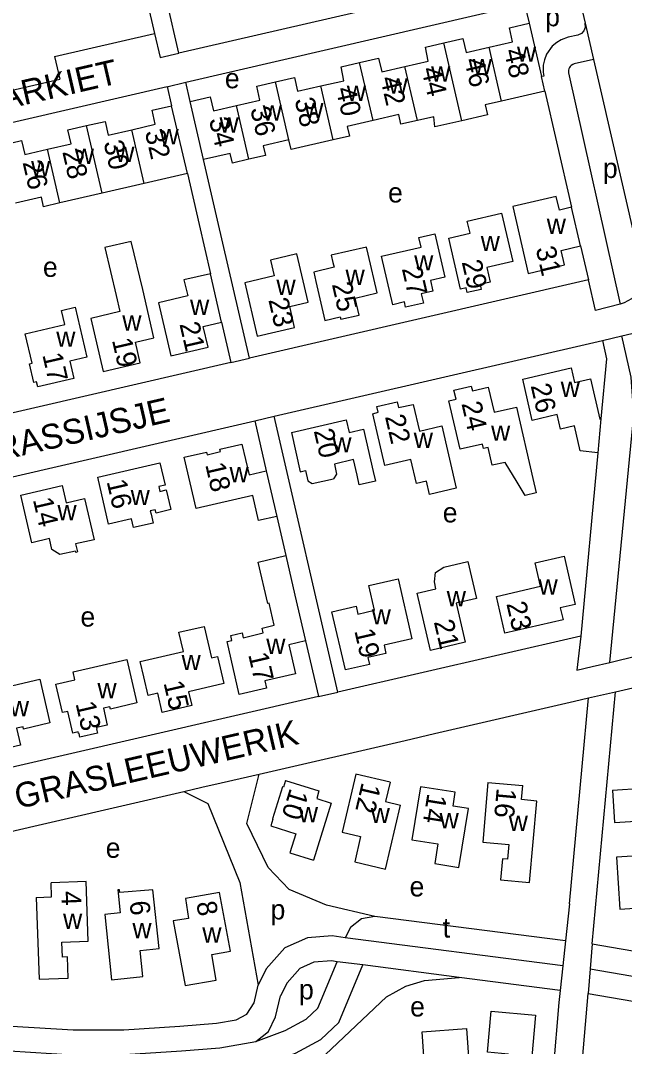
# Model space of a CAD drawing. Extents: x 155696 to 157795, y 382328 to 384028.
# Drawn here: x 156705.6 to 156827.2, y 383139.6 to 383346.1 of the extents above; entities that cross this region are included whole.
import ezdxf

# ---------------------------------------------------------------- set-up
doc = ezdxf.new("R2010")
doc.units = 0
for name, color, linetype in [('BLT_Basislijn', 7, 'Continuous'), ('BLT_Bebouwing', 7, 'Continuous'), ('BLT_Centroide', 7, 'Continuous'), ('BLT_Huisnummer', 7, 'Continuous'), ('BLT_Huisnummer_ tussenligend', 7, 'Continuous'), ('BLT_Onderverdeling_panden', 7, 'Continuous'), ('BLT_Straatnaam', 7, 'Continuous')]:
    doc.layers.add(name, color=color, linetype=linetype)

msp = doc.modelspace()

# ---------------------------------------------------------------- linework, layer by layer
at = {"layer": 'BLT_Basislijn'}
for p, q in [((156819.25, 383345.11), (156819.26, 383345.53)), ((156819.26, 383345.53), (156820.95, 383338.22)), ((156712.46, 383338.83), (156732.56, 383343.47)), ((156712.46, 383338.83), (156713.51, 383334.26)), ((156685.11, 383327.7), (156713.51, 383334.26)), ((156735.03, 383332.74), (156738.84, 383333.63)), ((156826.61, 383282.58), (156831.79, 383283.78)), ((156822.71, 383281.68), (156826.61, 383282.58)), ((156747.95, 383277.24), (156751.67, 383278.1)), ((156752.73, 383265.51), (156756.62, 383266.41)), ((156821.81, 383259.06), (156818.36, 383222.17)), ((156765.55, 383209.98), (156769.45, 383210.88)), ((156819.94, 383209.71), (156825.35, 383210.96)), ((156788.92, 383202.54), (156817.14, 383209.06)), ((156817.14, 383209.06), (156819.94, 383209.71)), ((156782.99, 383201.17), (156788.92, 383202.54)), ((156753.65, 383194.4), (156782.99, 383201.17)), ((156746.01, 383192.63), (156753.65, 383194.4)), ((156742.11, 383191.73), (156746.01, 383192.63)), ((156693.58, 383180.52), (156738.44, 383190.88)), ((156738.44, 383190.88), (156742.11, 383191.73)), ((156820.68, 383160.19), (156820.26, 383155.19)), ((156820.26, 383155.19), (156819.83, 383150.19)), ((156813.95, 383148.39), (156810.53, 383107.98))]:
    msp.add_line(p, q, dxfattribs=at)
for points in [[(156664.33, 383327.71), (156659.04, 383350.61), (156727.27, 383366.37), (156732.56, 383343.47)], [(156809.62, 383356.14), (156737.49, 383339.48), (156735.12, 383349.71)], [(156738.84, 383333.63), (156807.07, 383349.4)], [(156807.07, 383349.4), (156807.97, 383345.5)], [(156818.46, 383348.95), (156819.26, 383345.53)], [(156819.25, 383345.11), (156819.24, 383344.65), (156819.01, 383343.95), (156818.49, 383343.46), (156817.76, 383343.13), (156815.81, 383342.68), (156814.39, 383342.17), (156813.56, 383341.62), (156812.63, 383340.89), (156811.49, 383339.28), (156811.04, 383338.17), (156810.81, 383337.09), (156810.8, 383335.66), (156810.94, 383334.88), (156810.45, 383334.78)], [(156732.56, 383343.47), (156733.68, 383338.6), (156737.49, 383339.48)], [(156820.95, 383338.22), (156817.05, 383337.32), (156816.74, 383337.21), (156816.45, 383337.03), (156816.24, 383336.82), (156816.08, 383336.58), (156815.98, 383336.34), (156815.9, 383336.08), (156815.89, 383335.79), (156815.93, 383335.52), (156826.3, 383288.94)], [(156820.95, 383338.22), (156830.69, 383296.04), (156830.81, 383294.33), (156830.54, 383292.75), (156829.66, 383291.07), (156828.58, 383290.07), (156827.13, 383289.21), (156826.3, 383288.94)], [(156667.81, 383313.12), (156666.88, 383317.01), (156735.12, 383332.78)], [(156735.12, 383332.78), (156736.01, 383328.9)], [(156739.74, 383329.74), (156738.84, 383333.63)], [(156811.12, 383331.86), (156813.49, 383321.63)], [(156813.49, 383321.63), (156816.51, 383308.47)], [(156745.25, 383305.87), (156742.45, 383318.06)], [(156739.18, 383315.26), (156741.53, 383305.01)], [(156819.9, 383293.86), (156751.67, 383278.1), (156745.25, 383305.87)], [(156741.53, 383305.01), (156743.83, 383295.07)], [(156818.33, 383300.68), (156819.9, 383293.86)], [(156826.3, 383288.94), (156821.33, 383287.66), (156819.9, 383293.86)], [(156746.08, 383285.32), (156747.95, 383277.24), (156679.71, 383261.48), (156673.3, 383289.24)], [(156756.62, 383266.41), (156822.71, 383281.68)], [(156822.71, 383281.68), (156823.58, 383277.95), (156822.42, 383265.9)], [(156828.53, 383274.26), (156826.61, 383282.58)], [(156824.25, 383216.86), (156829.03, 383266.72), (156828.53, 383274.26)], [(156818.36, 383222.17), (156769.45, 383210.88), (156756.62, 383266.41)], [(156682.73, 383249.34), (156752.73, 383265.51), (156755.05, 383255.43)], [(156762.96, 383221.21), (156765.55, 383209.98), (156695.56, 383193.81), (156682.73, 383249.34)], [(156757.17, 383246.25), (156759, 383238.36)], [(156818.36, 383222.17), (156817.57, 383215.32), (156820.65, 383216.03), (156824.25, 383216.86)], [(156824.25, 383216.86), (156840.78, 383220.93)], [(156825.35, 383210.96), (156842.25, 383214.86)], [(156820.68, 383160.19), (156825.35, 383210.96)], [(156816.07, 383168.29), (156819.94, 383209.71)], [(156776.9, 383165.74), (156767.16, 383167.97), (156759.7, 383171.13), (156755.46, 383175.55), (156751.14, 383184.47), (156753.65, 383194.4)], [(156738.44, 383190.88), (156743.29, 383188.47), (156749.72, 383172.56), (156753.45, 383151.93)], [(156816.07, 383168.29), (156815.27, 383160.79)], [(156776.9, 383165.74), (156774.25, 383165.23), (156772.02, 383163.5), (156770.95, 383161.46)], [(156815.27, 383160.79), (156776.9, 383165.74)], [(156624.06, 383159.74), (156634.99, 383161.39), (156641.65, 383161.73), (156646.47, 383160.41), (156654.67, 383156.22), (156664.2, 383151.34), (156679.47, 383145.14), (156688.43, 383141.04), (156694.45, 383139.66), (156703.4, 383138.69), (156716.03, 383137.88), (156726.59, 383137.94), (156738.01, 383138.69), (156745.69, 383139.31), (156752.98, 383140.57)], [(156770.95, 383161.46), (156768.32, 383161.8), (156763.38, 383161.46), (156758.79, 383159.39), (156755.06, 383155.2), (156753.45, 383151.93)], [(156814.74, 383155.82), (156770.95, 383161.46)], [(156815.27, 383160.79), (156814.74, 383155.82)], [(156820.68, 383160.19), (156846.73, 383155.72)], [(156769.34, 383156.63), (156768.17, 383156.78), (156764.62, 383156.53), (156761.81, 383155.27), (156759.25, 383152.39), (156757.94, 383149.73)], [(156625.19, 383154.85), (156635.49, 383156.41), (156641.1, 383156.7), (156644.65, 383155.72), (156652.4, 383151.77), (156662.12, 383146.79), (156677.48, 383140.55), (156686.81, 383136.28), (156693.62, 383134.72), (156702.97, 383133.7), (156715.88, 383132.88), (156726.77, 383132.94), (156738.37, 383133.7), (156746.32, 383134.34), (156754.28, 383135.72), (156760.97, 383138.19), (156766.06, 383140.98), (156769.64, 383144.39), (156774.48, 383155.97)], [(156752.98, 383140.57), (156758.89, 383142.75), (156763.08, 383145.05), (156765.44, 383147.29), (156769.34, 383156.63)], [(156774.48, 383155.97), (156769.34, 383156.63)], [(156793.91, 383153.46), (156774.48, 383155.97)], [(156814.74, 383155.82), (156814.21, 383150.85)], [(156820.26, 383155.19), (156846.76, 383150.64)], [(156767.48, 383098.04), (156766.03, 383104.42), (156756.96, 383125.83), (156759.58, 383130.94), (156779.26, 383149.57), (156783.18, 383151.73), (156786.92, 383152.81), (156793.91, 383153.46)], [(156814.21, 383150.85), (156793.91, 383153.46)], [(156748.98, 383144.95), (156751.18, 383146.08), (156752.61, 383148.32), (156753.45, 383151.93)], [(156814.21, 383150.85), (156813.95, 383148.39)], [(156752.98, 383140.57), (156755.53, 383142.58), (156756.9, 383145.5), (156757.94, 383149.73)], [(156800.36, 383000.81), (156809.66, 383051.7), (156812.28, 383070.91), (156814.57, 383087.69), (156816.87, 383115.08), (156819.83, 383150.19)], [(156819.83, 383150.19), (156846.8, 383145.57)], [(156690.04, 383145.8), (156695.28, 383144.6), (156703.83, 383143.67), (156716.18, 383142.88), (156726.41, 383142.94), (156737.65, 383143.67), (156745.06, 383144.27), (156748.98, 383144.95)]]:
    msp.add_lwpolyline(points, dxfattribs=at)
at = {"layer": 'BLT_Bebouwing'}
for p, q in [((156807.97, 383345.5), (156810.45, 383334.78)), ((156790.81, 383341.55), (156794.61, 383342.44)), ((156794.61, 383342.44), (156795.27, 383339.61)), ((156795.27, 383339.61), (156799.93, 383340.7)), ((156770.14, 383336.76), (156773.86, 383337.61)), ((156770.7, 383333.94), (156770.14, 383336.76)), ((156811.12, 383331.86), (156810.45, 383334.78)), ((156753.19, 383332.84), (156756.9, 383333.7)), ((156753.78, 383330.04), (156753.19, 383332.84)), ((156766.02, 383332.88), (156770.7, 383333.94)), ((156732.07, 383327.99), (156736.01, 383328.9)), ((156739.18, 383315.26), (156736.01, 383328.9)), ((156742.45, 383318.06), (156739.74, 383329.74)), ((156749.07, 383328.95), (156753.78, 383330.04)), ((156732.72, 383325.2), (156732.07, 383327.99)), ((156715.11, 383324.06), (156718.85, 383324.92)), ((156715.76, 383321.27), (156715.11, 383324.06)), ((156718.85, 383324.92), (156722.61, 383325.76)), ((156722.61, 383325.76), (156723.27, 383322.97)), ((156723.27, 383322.97), (156727.98, 383324.08)), ((156727.98, 383324.08), (156732.72, 383325.2)), ((156760.06, 383320.08), (156759.61, 383322.03)), ((156768.53, 383322.04), (156760.06, 383320.08)), ((156711.02, 383320.16), (156715.76, 383321.27)), ((156818.33, 383300.68), (156816.51, 383308.47)), ((156758.91, 383193.11), (156765.67, 383191.02)), ((156799.67, 383192.69), (156806.68, 383192.06)), ((156768.16, 383188.54), (156764.59, 383177.06)), ((156779.05, 383175.25), (156782.06, 383188.14)), ((156808.03, 383172.55), (156809.53, 383188.94)), ((156793.83, 383175.61), (156795.74, 383187.46)), ((156708.74, 383169.56), (156709.33, 383153.09)), ((156722.55, 383166.1), (156723.93, 383152.97)), ((156736.34, 383164.82), (156738.74, 383151.81))]:
    msp.add_line(p, q, dxfattribs=at)
for points in [[(156799.93, 383340.7), (156804.61, 383341.78), (156804, 383344.58), (156807.97, 383345.5)], [(156782.98, 383336.79), (156787.67, 383337.87), (156787.09, 383340.67), (156790.81, 383341.55)], [(156773.86, 383337.61), (156777.68, 383338.49), (156778.32, 383335.71), (156782.98, 383336.79)], [(156756.9, 383333.7), (156760.72, 383334.6), (156761.35, 383331.82), (156766.02, 383332.88)], [(156739.74, 383329.74), (156743.79, 383330.67), (156744.43, 383327.89), (156749.07, 383328.95)], [(156811.12, 383331.86), (156802.44, 383329.85)], [(156802.44, 383329.85), (156799.13, 383329.09), (156799.59, 383327.09), (156794.42, 383325.9)], [(156785.48, 383325.95), (156782.18, 383325.17), (156781.73, 383327.12), (156776.55, 383325.94)], [(156794.42, 383325.9), (156789.02, 383324.65), (156788.79, 383326.7), (156785.48, 383325.95)], [(156776.55, 383325.94), (156771.38, 383324.73), (156771.84, 383322.8), (156768.53, 383322.04)], [(156759.61, 383322.03), (156754.43, 383320.83), (156754.89, 383318.88), (156751.57, 383318.12)], [(156701.9, 383321), (156705.8, 383321.9), (156706.44, 383319.1), (156711.02, 383320.16)], [(156751.57, 383318.12), (156748.28, 383317.36), (156747.83, 383319.31), (156742.45, 383318.06)], [(156739.18, 383315.26), (156730.48, 383313.25)], [(156730.48, 383313.25), (156722, 383311.29)], [(156713.52, 383309.33), (156710.24, 383308.56), (156709.79, 383310.52), (156704.61, 383309.32)], [(156722, 383311.29), (156713.52, 383309.33)], [(156816.51, 383308.47), (156814.07, 383307.91), (156813.44, 383310.64), (156804.69, 383308.61), (156807.8, 383295.17), (156815.1, 383296.86), (156814.43, 383299.78), (156818.33, 383300.68)], [(156730.19, 383291.92), (156727.87, 383301.59), (156722.56, 383300.35), (156724.86, 383290.69), (156725.6, 383287.47), (156719.72, 383286.11), (156722.2, 383275.4)], [(156743.83, 383295.07), (156738.5, 383293.84), (156739.25, 383290.62), (156733.36, 383289.26), (156735.84, 383278.55)], [(156746.08, 383285.32), (156743.83, 383295.07)], [(156732.44, 383282.17), (156730.19, 383291.92)], [(156735.84, 383278.55), (156743.35, 383280.28), (156742.38, 383284.47), (156746.08, 383285.32)], [(156722.2, 383275.4), (156729.71, 383277.13), (156728.74, 383281.32), (156732.44, 383282.17)], [(156818.25, 383259.42), (156817.08, 383264.46), (156814.28, 383263.81), (156813.6, 383266.73), (156808.6, 383265.57), (156806.68, 383273.87), (156816.42, 383276.12), (156817.1, 383273.2), (156820.31, 383273.93), (156822.2, 383265.85), (156822.42, 383265.9)], [(156792.84, 383271.67), (156796.34, 383272.47), (156796.56, 383271.5), (156799.75, 383272.24), (156800.91, 383267.2), (156805.41, 383268.24), (156808.73, 383253.89), (156809.36, 383250.99), (156807.18, 383250.49), (156805.54, 383253.15), (156803.14, 383257.09), (156800.56, 383256.55), (156799.71, 383260.15)], [(156799.71, 383260.15), (156798.79, 383259.93), (156798.58, 383260.79), (156794.06, 383259.76), (156791.8, 383269.49), (156793.27, 383269.84), (156792.84, 383271.67)], [(156760.11, 383263.11), (156771.14, 383265.66), (156771.72, 383263.16), (156774.62, 383263.82), (156776.59, 383255.31), (156777.02, 383253.34), (156773.77, 383252.6), (156773.37, 383254.57), (156772.65, 383257.68), (156768.79, 383256.79), (156769.18, 383254.72), (156768.61, 383253.83)], [(156822.42, 383265.9), (156821.81, 383259.06)], [(156760.11, 383263.11), (156761.92, 383255.24), (156762.95, 383255.47), (156763.43, 383253.41), (156764.33, 383252.84), (156768.61, 383253.83)], [(156757.17, 383246.25), (156753.5, 383245.41), (156752.34, 383250.45), (156740.96, 383247.82), (156738.57, 383258.14), (156743.02, 383259.18), (156743.14, 383258.66), (156745.87, 383259.29), (156745.75, 383259.81), (156750.17, 383260.82), (156751.6, 383254.63), (156755.05, 383255.43)], [(156821.81, 383259.06), (156818.25, 383259.42)], [(156755.05, 383255.43), (156757.17, 383246.25)], [(156755.35, 383228.73), (156753.44, 383237.06), (156759, 383238.36)], [(156759, 383238.36), (156760.84, 383230.39)], [(156760.84, 383230.39), (156762.96, 383221.21)], [(156749.6, 383210.4), (156747.18, 383221.08), (156748.13, 383221.3), (156747.91, 383222.27), (156750.2, 383222.8), (156750.43, 383221.82), (156754.47, 383222.81), (156754.24, 383223.78), (156756.67, 383224.34), (156755.65, 383228.8), (156755.35, 383228.73)], [(156762.96, 383221.21), (156759.6, 383220.43), (156760.96, 383214.56), (156754.76, 383213.13)], [(156754.76, 383213.13), (156755.1, 383211.66), (156749.6, 383210.4)], [(156779.97, 383192.77), (156773.1, 383194.37), (156770.35, 383182.7), (156774.04, 383181.83), (156772.89, 383176.71), (156779.05, 383175.25)], [(156758.91, 383193.11), (156758.5, 383191.77), (156758.32, 383191.83), (156756.31, 383185.36), (156756.39, 383185.34), (156755.96, 383183.96), (156761.03, 383182.39), (156759.83, 383178.53), (156764.59, 383177.06)], [(156779.97, 383192.77), (156779.05, 383188.84), (156782.06, 383188.14)], [(156799.67, 383192.69), (156798.64, 383180.7), (156803.86, 383180.21), (156803.59, 383177.26), (156802.59, 383177.35), (156802.19, 383173.09), (156808.03, 383172.55)], [(156809.53, 383188.94), (156806.43, 383189.24), (156806.68, 383192.06)], [(156765.67, 383191.02), (156765.21, 383189.44), (156768.16, 383188.54)], [(156793.09, 383190.73), (156786.13, 383191.85), (156784.37, 383181.17), (156789.61, 383180.37), (156789, 383176.39), (156793.83, 383175.61)], [(156795.74, 383187.46), (156792.66, 383187.94), (156793.09, 383190.73)], [(156824.75, 383191.16), (156830.86, 383191.55), (156830.99, 383189.5), (156833.78, 383189.68)], [(156824.75, 383191.16), (156825.17, 383184.64), (156829.42, 383184.91), (156829.86, 383177.95), (156825.58, 383177.67), (156826.25, 383167.21), (156835.24, 383167.79), (156833.78, 383189.68)], [(156708.74, 383169.56), (156711.86, 383169.69), (156711.76, 383172.52)], [(156709.33, 383153.09), (156715.19, 383153.31), (156715.03, 383157.59), (156714.05, 383157.55), (156713.94, 383160.55), (156719.22, 383160.74), (156718.81, 383172.74), (156711.76, 383172.52)], [(156723.93, 383152.97), (156730.24, 383153.64), (156729.69, 383158.85), (156733.49, 383159.26), (156732.23, 383171.12), (156725.62, 383170.54), (156725.55, 383171.09), (156725.16, 383171.06), (156725.66, 383166.44), (156722.55, 383166.1)], [(156738.8, 383169.36), (156739.42, 383165.35), (156736.34, 383164.82)], [(156738.74, 383151.81), (156744.99, 383152.92), (156744.09, 383158.07), (156747.86, 383158.75), (156745.65, 383170.54), (156738.8, 383169.36)]]:
    msp.add_lwpolyline(points, dxfattribs=at)
for points in [[(156791.79, 383302.25), (156796.09, 383303.24), (156795.53, 383305.68), (156802.43, 383307.27), (156804.68, 383297.53), (156799.47, 383296.32), (156800.15, 383293.4), (156798.1, 383292.93), (156798.32, 383291.95), (156795.5, 383291.3), (156795.27, 383292.28), (156794.15, 383292.02)], [(156778.26, 383298.61), (156786.23, 383300.45), (156785.78, 383302.4), (156789.02, 383303.14), (156791.04, 383294.38), (156788.12, 383293.7), (156788.61, 383291.59), (156786.26, 383291.04), (156786.69, 383289.17), (156783.11, 383288.34), (156782.86, 383289.41), (156780.51, 383288.86)], [(156775.6, 383299.02), (156775.25, 383300.47), (156768.16, 383298.82), (156768.49, 383297.38), (156768.72, 383296.39), (156764.63, 383295.44), (156765.07, 383293.51), (156766.87, 383285.71), (156769.94, 383286.42), (156770.05, 383285.94), (156773.73, 383286.78), (156772.94, 383290.19), (156777.4, 383291.23)], [(156761.22, 383299.08), (156755.89, 383297.85), (156756.64, 383294.64), (156750.76, 383293.28), (156753.23, 383282.56), (156760.74, 383284.3), (156759.78, 383288.49), (156763.47, 383289.34)], [(156716.61, 383288.35), (156718.94, 383278.32), (156715.53, 383277.52), (156716.35, 383274.02), (156709.05, 383272.31), (156708.81, 383273.31), (156708.29, 383273.2), (156707.42, 383276.97), (156707.93, 383277.09), (156706.56, 383283.01), (156714.53, 383284.86), (156713.87, 383287.72)], [(156776.51, 383266.9), (156777.6, 383267.21), (156777.33, 383268.39), (156781.4, 383269.34), (156781.68, 383268.16), (156784.65, 383268.75), (156785.88, 383263.42), (156790.38, 383264.46), (156793.27, 383251.93), (156787.93, 383250.69), (156787.31, 383253.37), (156785.27, 383252.9), (156784.16, 383257.73), (156778.9, 383256.51)], [(156733.67, 383257.03), (156734.7, 383252.56), (156733.41, 383252.27), (156733.64, 383251.27), (156734.93, 383251.57), (156735.84, 383247.61), (156732.87, 383246.93), (156732.72, 383247.59), (156731.72, 383247.36), (156731.87, 383246.69), (156732.28, 383244.92), (156728.33, 383244), (156727.93, 383245.74), (156723.33, 383244.68), (156721.15, 383254.12)], [(156705.69, 383250.54), (156713.97, 383252.46), (156714.77, 383248.99), (156718.47, 383249.84), (156720.39, 383241.56), (156716.69, 383240.71), (156717.05, 383239.12), (156716.72, 383239), (156716.67, 383239.22), (156713.49, 383238.57), (156711.92, 383239.6), (156711.42, 383241.77), (156707.9, 383240.96)], [(156801.39, 383230.14), (156810.25, 383232.18), (156809.17, 383236.89), (156815.01, 383238.24), (156817.25, 383228.54), (156814.25, 383227.84), (156814.8, 383225.46), (156803.09, 383222.75)], [(156785.42, 383230.82), (156789.22, 383231.7), (156788.91, 383233.05), (156789.16, 383234.99), (156790.79, 383236.06), (156795.65, 383237.19), (156797.37, 383229.74), (156793.28, 383228.8), (156795.1, 383220.91), (156788.09, 383219.28)], [(156775.85, 383216.46), (156770.99, 383215.34), (156768.29, 383227.03), (156773.16, 383228.15), (156773.52, 383226.59), (156776.84, 383227.36), (156775.7, 383232.32), (156781.58, 383233.68), (156784.37, 383221.61), (156778.77, 383220.32), (156779.15, 383218.66), (156775.54, 383217.82)], [(156734.1, 383206.81), (156733.22, 383210.67), (156731.3, 383210.22), (156730.41, 383213.97), (156729.7, 383217.02), (156738.37, 383219.05), (156737.47, 383222.94), (156742.55, 383224.11), (156744.01, 383217.77), (156745.26, 383218.06), (156746.53, 383212.6), (156739.42, 383210.96), (156740.06, 383208.19)], [(156715.11, 383207), (156714.05, 383206.76), (156712.71, 383212.47), (156716.56, 383213.36), (156716.19, 383214.99), (156726.98, 383217.48), (156729, 383208.72), (156723.71, 383207.46), (156723.6, 383207.95), (156722.28, 383207.65), (156723.07, 383204.25), (156720.89, 383203.75), (156720.95, 383203.42), (156720.89, 383203.41), (156721.07, 383202.63), (156717.55, 383201.81), (156717.37, 383202.58), (156717.3, 383202.57), (156717.23, 383202.89), (156716.11, 383202.63)], [(156695.15, 383208.27), (156698.98, 383209.15), (156698.57, 383210.95), (156709.48, 383213.47), (156711.51, 383204.68), (156706.23, 383203.43), (156706.12, 383203.91), (156704.8, 383203.61), (156705.58, 383200.2), (156698.62, 383198.59), (156697.57, 383202.95), (156696.5, 383202.69)], [(156800.32, 383146.68), (156809.28, 383145.88), (156807.54, 383126.23), (156801.53, 383126.76), (156801.94, 383131.45), (156803.21, 383131.34), (156803.8, 383138.02), (156799.58, 383138.39)], [(156786.42, 383142.53), (156795.4, 383143.15), (156797.06, 383119.23), (156788.07, 383118.61), (156787.64, 383124.75), (156791.9, 383125.05), (156791.41, 383132.03), (156787.17, 383131.73)]]:
    msp.add_lwpolyline(points, close=True, dxfattribs=at)
at = {"layer": 'BLT_Onderverdeling_panden'}
for p, q in [((156794.42, 383325.9), (156790.81, 383341.55)), ((156802.44, 383329.85), (156799.93, 383340.7)), ((156776.55, 383325.94), (156773.86, 383337.61)), ((156785.48, 383325.95), (156782.98, 383336.79)), ((156759.61, 383322.03), (156756.9, 383333.7)), ((156768.53, 383322.04), (156766.02, 383332.88)), ((156751.57, 383318.12), (156749.07, 383328.95)), ((156722, 383311.29), (156718.85, 383324.92)), ((156730.48, 383313.25), (156727.98, 383324.08)), ((156713.52, 383309.33), (156711.02, 383320.16))]:
    msp.add_line(p, q, dxfattribs=at)

# ---------------------------------------------------------------- texts
at = {"layer": 'BLT_Centroide'}
for s, p in [('p', (156811.2, 383344.9)), ('w', (156805.53, 383337.75)), ('w', (156788.25, 383333.75)), ('w', (156796.62, 383335.25)), ('e', (156746.73, 383332.42)), ('w', (156779.67, 383331.34)), ('w', (156771.28, 383329.86)), ('w', (156754.34, 383325.92)), ('w', (156762.72, 383326.41)), ('w', (156745.66, 383323.48)), ('w', (156733.58, 383321.16)), ('w', (156716.52, 383317.2)), ('w', (156724.67, 383317.59)), ('w', (156707.72, 383314.72)), ('p', (156822.83, 383314.36)), ('e', (156779.58, 383309.43)), ('w', (156811.52, 383303.11)), ('w', (156798.23, 383299.64)), ('e', (156710.11, 383294.46)), ('w', (156784.83, 383295.75)), ('w', (156771.02, 383292.83)), ('w', (156757.11, 383290.8)), ('w', (156739.72, 383286.78)), ('w', (156726.08, 383283.62)), ('w', (156712.79, 383280.38)), ('w', (156814.33, 383270.28)), ('w', (156800.31, 383261.47)), ('w', (156768.37, 383259.12)), ('w', (156784.75, 383260)), ('w', (156747.66, 383253.12)), ('w', (156727.76, 383248.52)), ('w', (156713.03, 383245.48)), ('e', (156790.59, 383245.04)), ('w', (156809.87, 383230.5)), ('w', (156791.39, 383228.14)), ('e', (156717.66, 383224.07)), ('w', (156776.29, 383224.5)), ('w', (156755.06, 383218.58)), ('w', (156738.01, 383215.31)), ('w', (156721.08, 383209.66)), ('w', (156703.45, 383206.03)), ('w', (156761.61, 383184.66)), ('w', (156776.09, 383184.52)), ('w', (156789.95, 383183.45)), ('w', (156803.86, 383182.94)), ('e', (156722.75, 383177.54)), ('e', (156783.91, 383169.76)), ('p', (156755.93, 383165.12)), ('w', (156714.16, 383163.23)), ('t', (156790.58, 383161.47)), ('w', (156728.12, 383161.36)), ('w', (156742.19, 383160.45)), ('p', (156761.66, 383149.04)), ('e', (156784.02, 383145.6))]:
    msp.add_text(s, height=4, dxfattribs=at).set_placement(p)
at = {"layer": 'BLT_Huisnummer'}
for s, rotation, p in [('48', 283.0054, (156802.88, 383339.97)), ('44', 283.0054, (156786.27, 383336.29)), ('42', 283.0054, (156777.97, 383334.43)), ('38', 283.0054, (156760.74, 383330.12)), ('34', 283.0054, (156743.51, 383326.13)), ('32', 283.0054, (156730.6, 383323.65)), ('30', 283.0054, (156722.29, 383321.51)), ('26', 283.0054, (156705.99, 383317.51)), ('31', 283.009, (156809.27, 383300.18)), ('29', 283.0052, (156794.38, 383297.47)), ('27', 283.0064, (156782.33, 383296.12)), ('25', 283.0064, (156768.25, 383292.97)), ('23', 283.0064, (156755.47, 383289.84)), ('21', 283.0064, (156737.57, 383284.97)), ('19', 283.0064, (156723.98, 383281.74)), ('17', 283.0739, (156709.97, 383278.77)), ('26', 283.0062, (156808.26, 383272.58)), ('24', 283.0031, (156794.33, 383268.97)), ('22', 283.0031, (156778.94, 383266.35)), ('20', 283.0031, (156764.6, 383263.49)), ('18', 283.0031, (156742.76, 383256.68)), ('16', 283.0031, (156722.91, 383253.28)), ('14', 283.0031, (156708.07, 383249.64)), ('23', 283.0051, (156803.37, 383228.7)), ('21', 283.0102, (156788.77, 383225.05)), ('19', 283.0102, (156772.77, 383223.24)), ('17', 283.0102, (156751.41, 383218.45)), ('15', 283.0102, (156734.36, 383212.75)), ('13', 283.0102, (156716.65, 383208.59)), ('12', 256.8128, (156774.32, 383192.86)), ('10', 252.8128, (156759.86, 383191.69)), ('14', 260.8128, (156787.52, 383190.61)), ('16', 264.8128, (156801.47, 383191.67)), ('4', 272.0059, (156713.78, 383170.8)), ('6', 276.0059, (156727.54, 383168.72)), ('8', 280.0059, (156740.96, 383168.49))]:
    msp.add_text(s, height=4, rotation=rotation, dxfattribs=at).set_placement(p)
at = {"layer": 'BLT_Huisnummer_ tussenligend'}
for s, p in [('46', (156794.88, 383338.13)), ('40', (156769.04, 383332.28)), ('36', (156751.82, 383328.28)), ('28', (156713.99, 383319.65))]:
    msp.add_text(s, height=4, rotation=283.0054, dxfattribs=at).set_placement(p)
at = {"layer": 'BLT_Straatnaam'}
for s, rotation, p in [('GRASPARKIET', 13.0063, (156679.2, 383322.75)), ('GRASSIJSJE', 13.0062, (156696.16, 383256.19)), ('GRASLEEUWERIK', 13.0069, (156705.05, 383187.35))]:
    msp.add_text(s, height=5, rotation=rotation, dxfattribs=at).set_placement(p)

doc.saveas('drawing.dxf')
